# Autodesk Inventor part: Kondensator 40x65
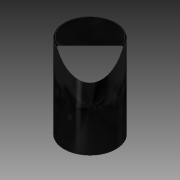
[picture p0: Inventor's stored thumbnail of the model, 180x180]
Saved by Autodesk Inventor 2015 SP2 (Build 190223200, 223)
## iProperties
Created: 2012-08
Part Number: Kondensator 40x65
Material: PC/ABS-Kunststoff
Document SubType Name: Modeling
Designer: rYan
Density: 1.493 g/cm^3
Mass: 121.967 g
Surface Area: 107.024 cm^2
Volume: 81.6924 cm^3
Appearance: Glänzend - schwarz
Author: rYan
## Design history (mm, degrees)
sketch "Skizze1"
  geometry: C1 r 20 at (0, 0); 1 further point
  constraints: 1 centre point, 1 coincident
  dimensions: "d0" = 40 diameter of C1
extrude "Extrusion1" new body sketch "Skizze1" distance "d1" = 65; taper "d2" = 0 deg
fillet "Rundung1" dims "d3" = 1
sketch "Skizze2"
  geometry: L1 (-28, 0)-(28, 0) reference; L2 (0, -28)-(0, 28) reference; C1 r 1 at (-5, 0); C2 r 1 at (5, 0); 2 further points
  constraints: 2 centre point, 2 coincident, 2 point on line, 1 symmetric about line, 1 other
  dimensions: "d4" = 10 distance of point (5, 0) point (-5, 0); "d5" = 2 diameter of C1
extrude "Extrusion2" join sketch "Skizze2" distance "d6" = 6; taper "d7" = 0 deg
workplane "Arbeitsebene1"
node "Volumenkörper1"
other parameters: "d8" = 0
